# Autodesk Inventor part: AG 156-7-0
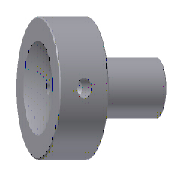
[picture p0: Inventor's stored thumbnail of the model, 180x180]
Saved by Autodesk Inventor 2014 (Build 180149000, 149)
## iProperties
IsCustomPart: 1
Created: 2009-11
Part Number: AG 156-7-0
Material: DIN 1.2312
Description: Sprue Bushing
Document SubType Name: Modeling
Designer: gaom
Standard Revision: 1
Manufacturer: DME
Language: en-US
Size Designation: 156-7-0
Categories: <MemberInstance><Categories><Category DisplayName="Mold" InternalName="349578f2-f4d4-4954-8c09-8e99297a61c0" Mnemonic="MOLD"><Category DisplayName="Runners" Int
Density: 7.85 g/cm^3
Appearance: Default
Author: gaom
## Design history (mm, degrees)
sketch "Sketch1"
  geometry: L1 (0, -27.2)-(0, 23.2) reference; L2 (3.5, 26)-(25, 26); L3 (25, 26)-(25, 0); L4 (25, 0)-(15.5, 0); L5 (12.5, -3)-(12.5, -156); L6 (12.5, -156)-(6.677, -156); L7 (6.677, -156)-(3.5, 26); A1 r 3 centre (15.5, -3) between (15.5, 0) and (12.5, -3); 2 further points
  constraints: 12 end point, 3 parallel, 2 perpendicular, 2 point on circle, 2 point on line, 2 tangent, 1 centre point
  dimensions: "d0" = 25 diameter of L5 L1 (= D); "d3" = 50 diameter of L3 L1 (= d1); "d6" = 1 deg angle of L7 L1 (= 0.5 x Taper); "d7" = 26 distance between parallel lines of L4 L2 (= K_); "d8" = 156 distance between parallel lines of L4 L6 (= L); "d9" = 3 radius of A1 (= R3); "d62" = 7 diameter of point (3.5, 26) L1 (= d_); "d63" = 0 distance from line of point (3.5, 26) L2 (computed from Rd)
revolve "Revolution1" sketch "Sketch1" stored, may be unused: angle "d10" = 90 deg
sketch "Sketch2"
  geometry: L1 (0, -32.79)-(0, 56.739) reference; L2 (6.677, -156)-(3.5, 26) reference; L3 (-25, 26)-(25, 26) reference; L4 (0, 56.6)-(0, 25.6); A1 r 15.5 centre (0, 41.1) between (0, 25.6) and (0, 56.6); 2 further points
  constraints: 3 point on circle, 3 point on line, 2 end point, 1 centre point, 1 midpoint
  dimensions: "d64" = 0 distance from line of point (3.5, 26) L3 (computed from Rd); "d67" = 15.5 radius of A1 (= Rk)
revolve "Revolution2" sketch "Sketch2" stored, may be unused: angle "d13" = 90 deg
workplane "Work Plane1"
sketch "Sketch3"
  geometry: 2 further points
  constraints: 1 vertical alignment
  dimensions: "d43" = 13 distance of point (0, -13) point (0, 0) (= 0.5 x K_)
hole "Hole1" sketch "Sketch3" at (0, 0) diameter "d15" = 4 (= pd1); stored, may be unused: countersink angle "d19" = 90 deg, drill point angle "d21" = 118 deg; dims "d16" = 6, "d17" = 4, "d18" = 2, "d20" = 6 (= pl1)
chamfer "Chamfer1" distance "d22" = 0.3; stored, may be unused: second distance "d23" = 2, angle "d24" = 45 deg
sketch "Sketch4"
  geometry: L1 (0, -30.4)-(0, 42.4) reference; L2 (0, 52)-(25.5, 52); L3 (25.5, 52)-(25.5, 0); L4 (12.5, -156)-(0, -156); L5 (0, -156)-(0, 52); L6 (12.5, -3)-(12.5, -156); L7 (15.5, 0)-(25.5, 0); L8 (15.5, 0)-(12.5, -3); 2 further points
  constraints: 14 end point, 4 point on line, 2 horizontal, 2 parallel, 1 perpendicular, 1 vertical
  dimensions: "d56" = 3 distance of L7.start point (12.5, 0) (= R3_CS); "d57" = 3 distance of L6.start point (12.5, 0) (= d56); "d58" = 51 diameter of L3 L1 (= d1_CS); "d59" = 52 distance between parallel lines of L7 L2 (= K_CS); "d60" = 25 diameter of L6 L1 (= D_CS); "d61" = 156 distance between parallel lines of L7 L4 (= L_CS)
feature "RevolutionSrf1" sketch "Sketch4" dims angle "d33" = 90 deg
feature "Sculpt1"
split "Split1"
body "Solid1"
body "Srf1"
feature "Surface1"
body "Srf2"
other parameters: "L" = 156 [user parameter; used in 1 equation term], "d1" = 50 [user parameter; used in 1 equation term], "d_" = 7 [user parameter; used in 1 equation term], "D" = 25 [user parameter; used in 1 equation term], "K_" = 26 [user parameter; used in 2 equation terms], "R" = 0 [user parameter], "Taper" = 2 deg [user parameter; used in 1 equation term], "Rd" = 0 [user parameter; used in 2 equation terms], "R3" = 3 [user parameter; used in 1 equation term], "pd1" = 4 [user parameter; used in 1 equation term], "d1_CS" = 51 [user parameter; used in 1 equation term], "K_CS" = 52 [user parameter; used in 1 equation term], "d44" = 0, "d45" = 0, "d46" = 0, "L_CS" = 156 [user parameter; used in 1 equation term], "D_CS" = 25 [user parameter; used in 1 equation term], "pl1" = 6 [user parameter; used in 1 equation term], "R3_CS" = 3 [user parameter; used in 1 equation term], "Rk" = 15.5 [user parameter; used in 1 equation term]
